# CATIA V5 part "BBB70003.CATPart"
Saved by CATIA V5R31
Part number: BBB70003
Revision: 1
Nomenclature: BRKT_C
Source: Unknown
Property "部品番号(A社)": "BBB70003"
Property "部品名称(A社)": "BRKT_C"
Property "Version(A社)": "1"
Property "材質": "JSH270C"
Property "板厚": "2.3"
Bounding box of the stored display mesh (mm): x -629.98 to -607.891, y -33.401 to 1.599, z -18.305 to 38.226
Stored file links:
  \\cad-nas02\CATIA1212\BODY_DEPARTMENT8\JAMA\変換データ\STEP3_最終_20240115\01_いすゞ板金\new_ファイル名修正後\CATIA_V5_20240122\BBB70003.CATPart
  \\damia-fs02\dept\DDE_Design\10_order\2305701_JAMA_変換検証STEP3_お手本モデル作成\work\01_いすゞ板金\10_CATIA_V5\bre30491.geo_fin001.001000_1.CATPart
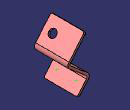
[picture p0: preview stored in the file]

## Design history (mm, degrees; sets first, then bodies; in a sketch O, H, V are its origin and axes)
Set1
  DatumPoint1
  DatumPoint2
Body1 "MANIFOLD_SOLID_BREP #328" (main body)
  Solid1: solid without history
  Sketch1 on face of Solid1, origin (-348.0392, 0, -292.0396), H (0, 1, 0), V (-0.6428, 0, 0.766)
    circle A1 centre (-23.4008, 418.3313) radius 4
    reference projected arc E1 centre (-23.4008, 418.3313) radius 3 from (-23.4008, 415.3313) to (-23.4008, 421.3313) ccw from edge [face of Solid1 | face of Solid1]
    radius A1 = 4
    concentricity: E1 A1
  Pocket1: profile Sketch1, direction (-0.766, 0, -0.6428), length 20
